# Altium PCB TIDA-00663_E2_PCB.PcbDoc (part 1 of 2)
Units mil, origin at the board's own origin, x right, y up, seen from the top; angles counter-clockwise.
Board outline 1968.5 x 1968.5 mil, 4 copper layers (Top Layer, Mid-Layer 1, Mid-Layer 2, Bottom Layer), stack 90 mil thick; 73 components, 52 nets, 290 pads, 111 vias.
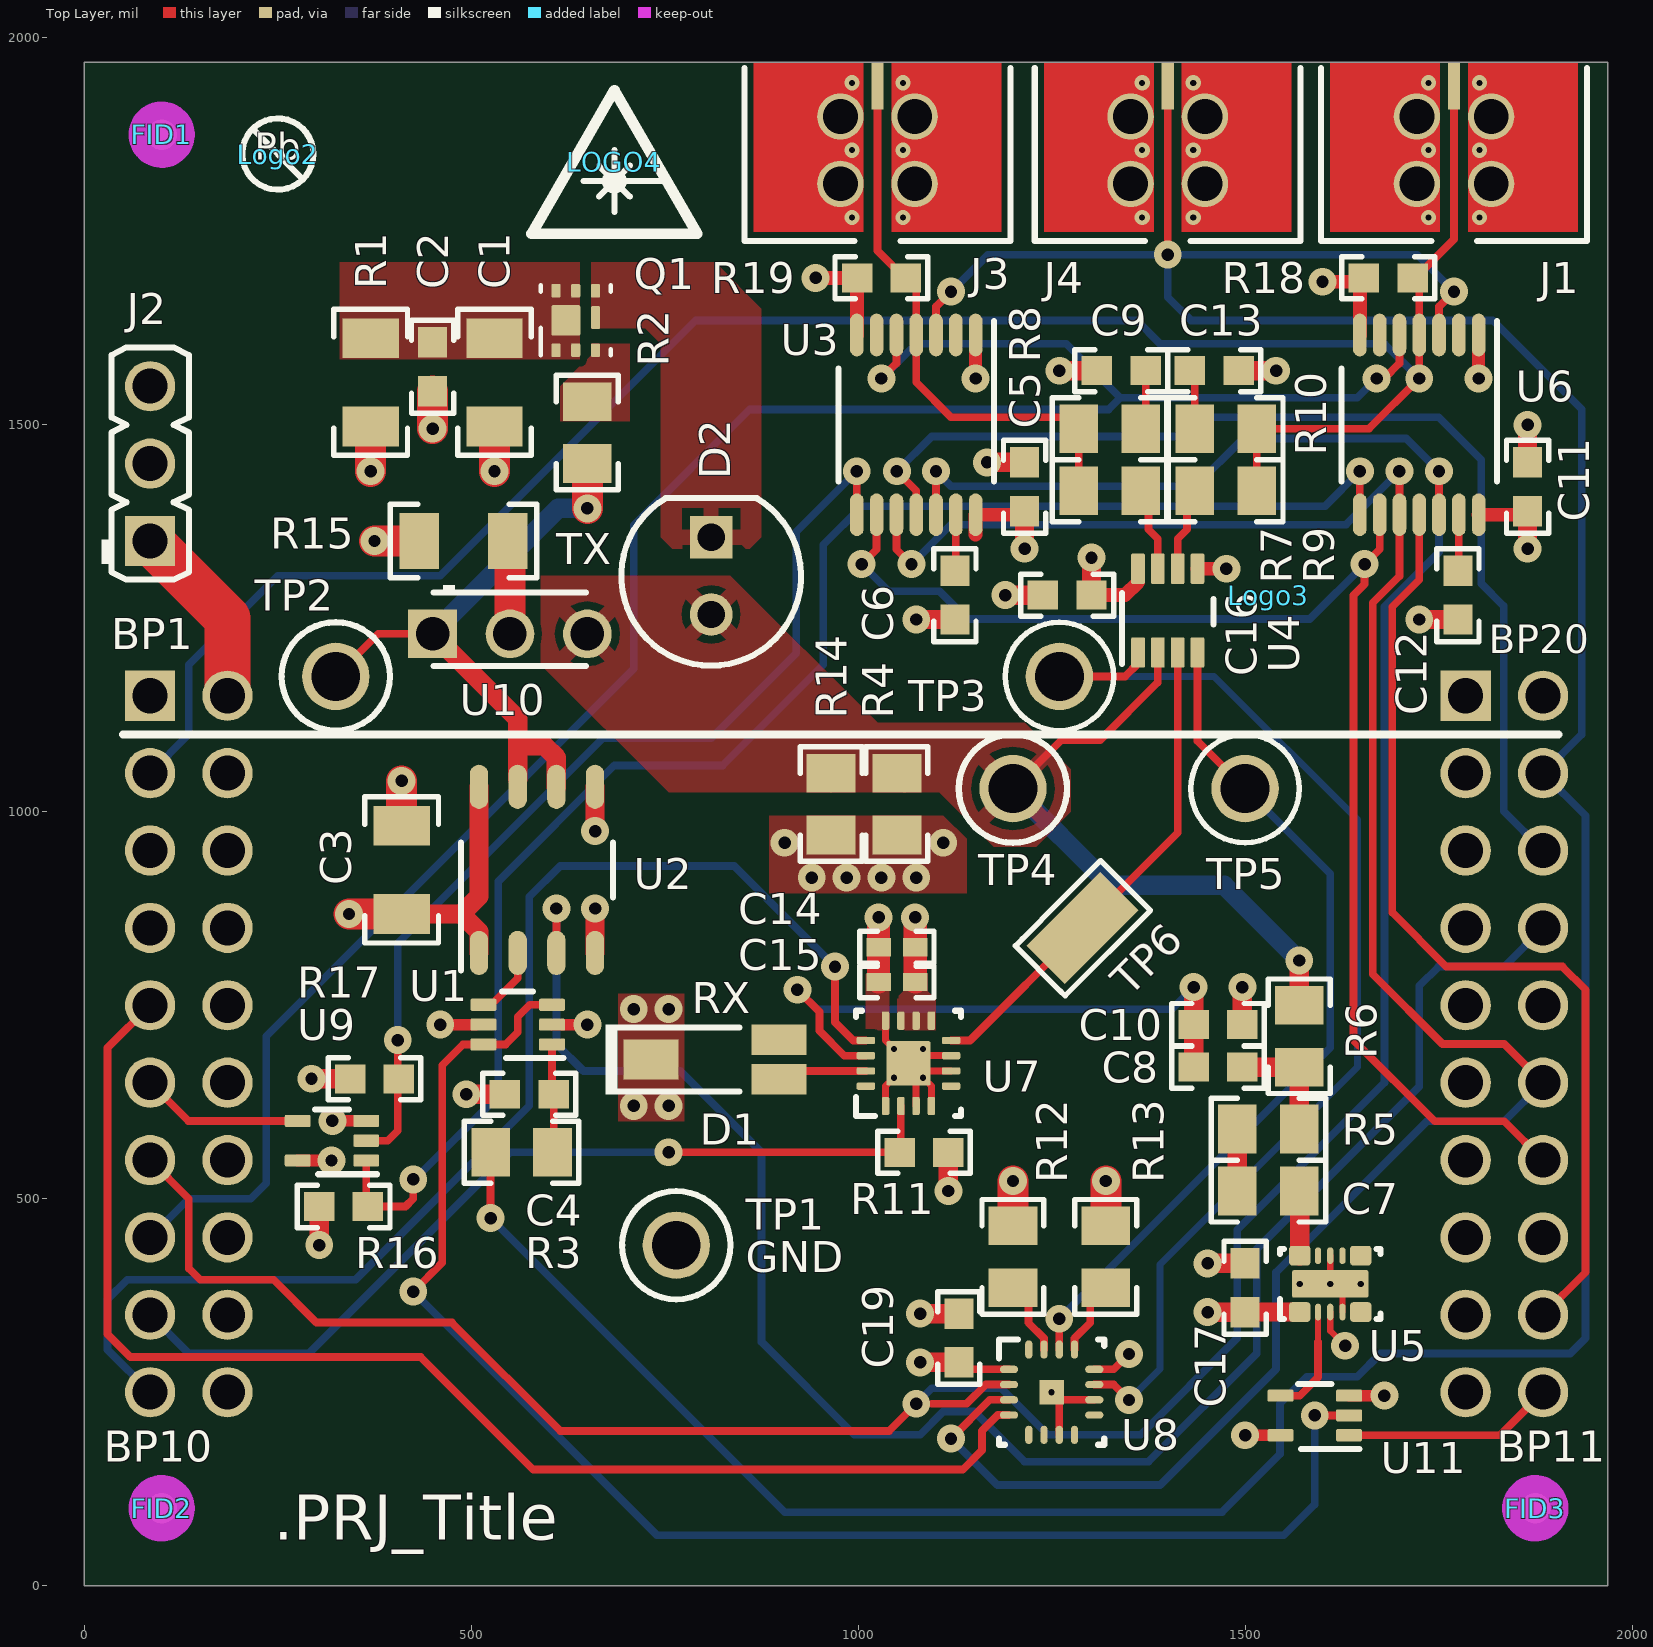
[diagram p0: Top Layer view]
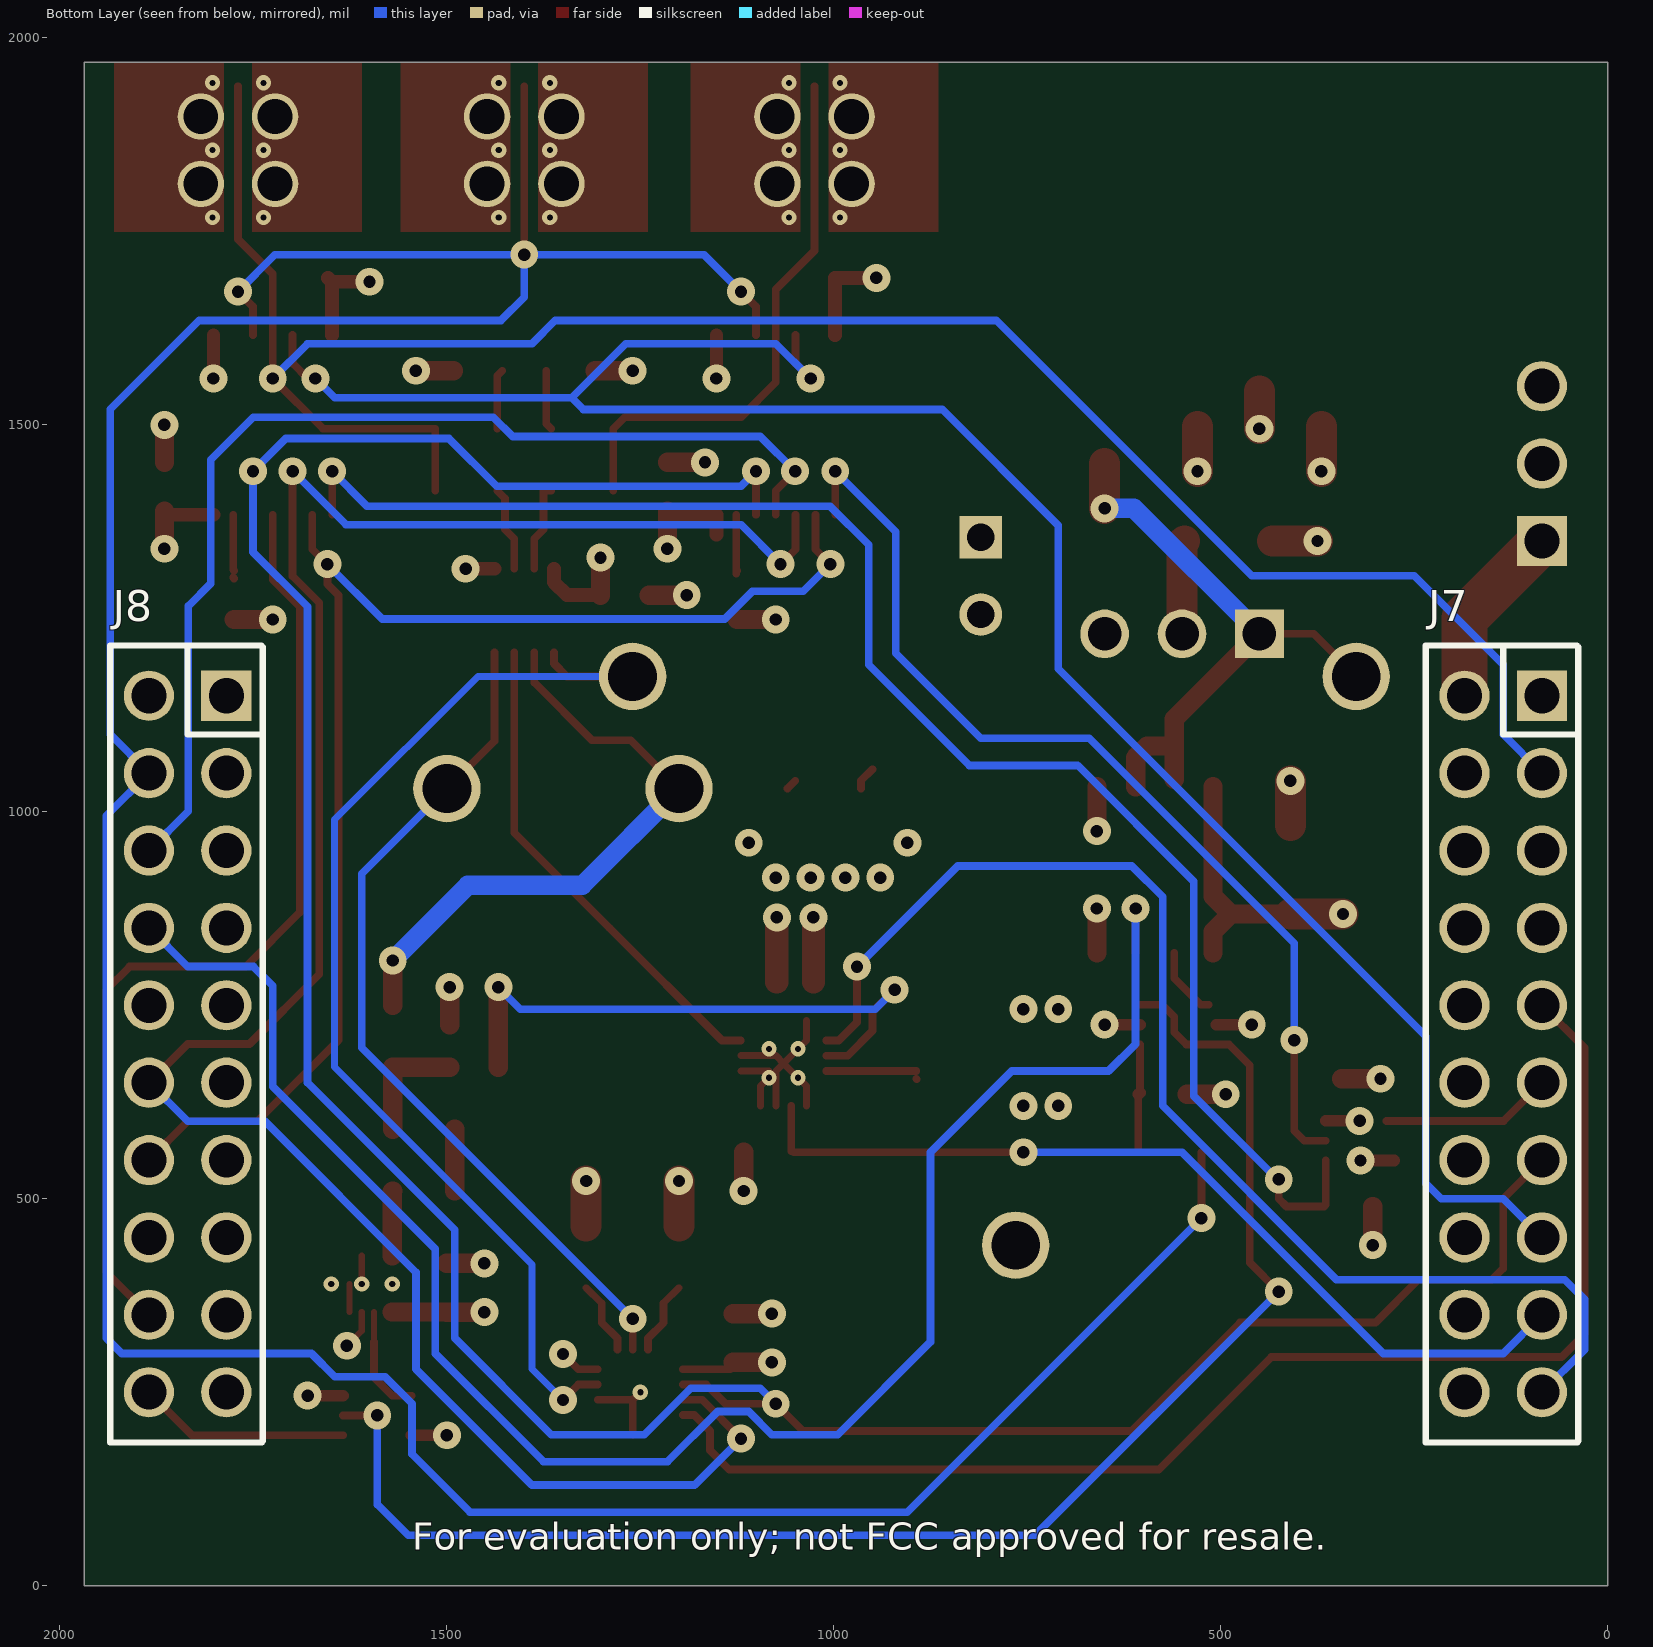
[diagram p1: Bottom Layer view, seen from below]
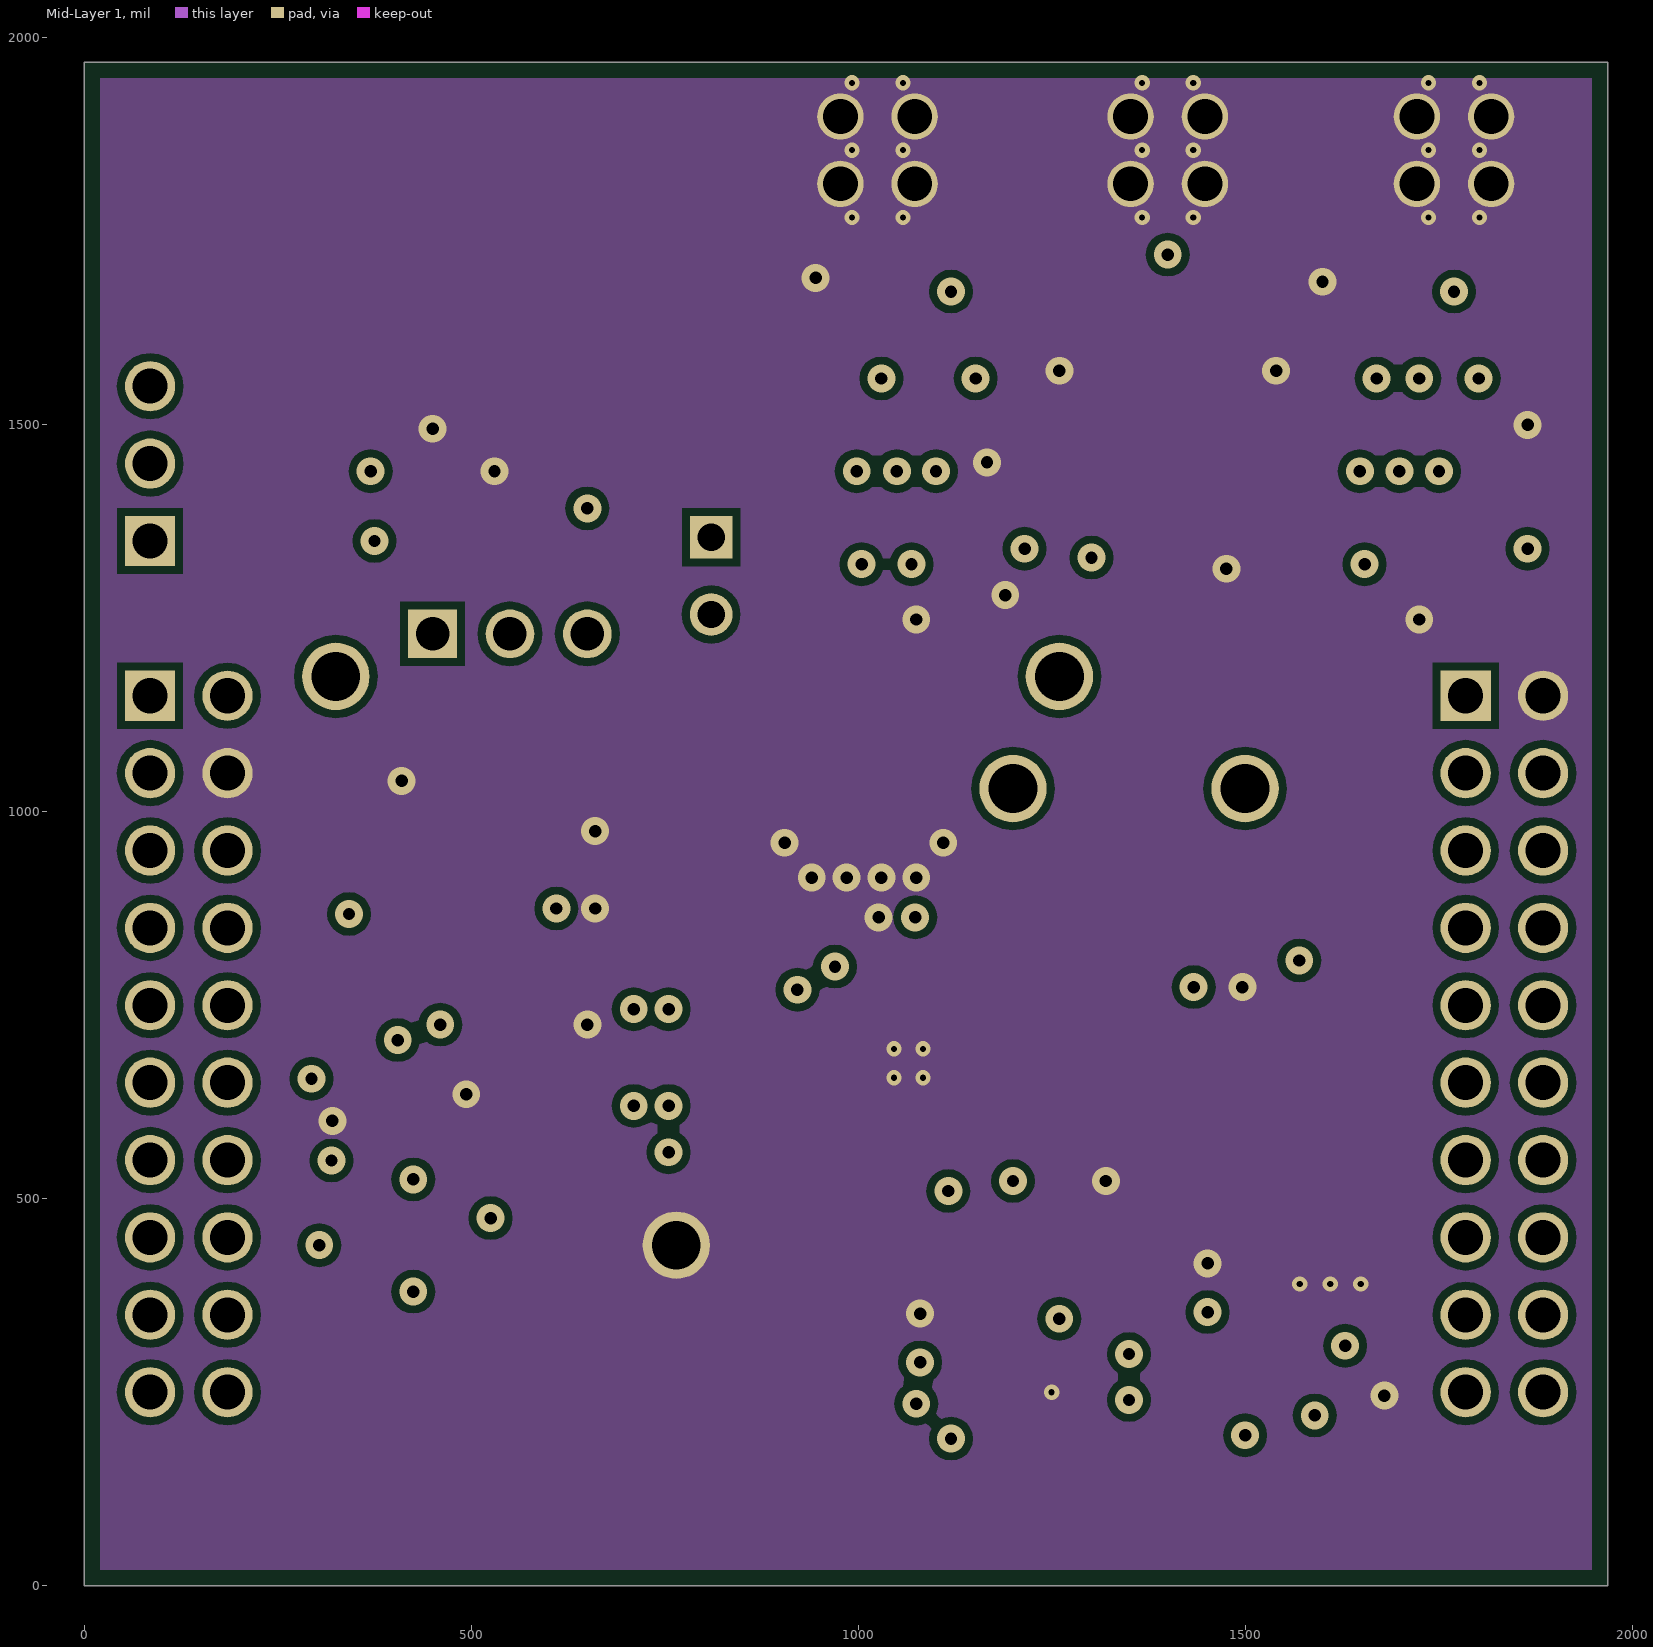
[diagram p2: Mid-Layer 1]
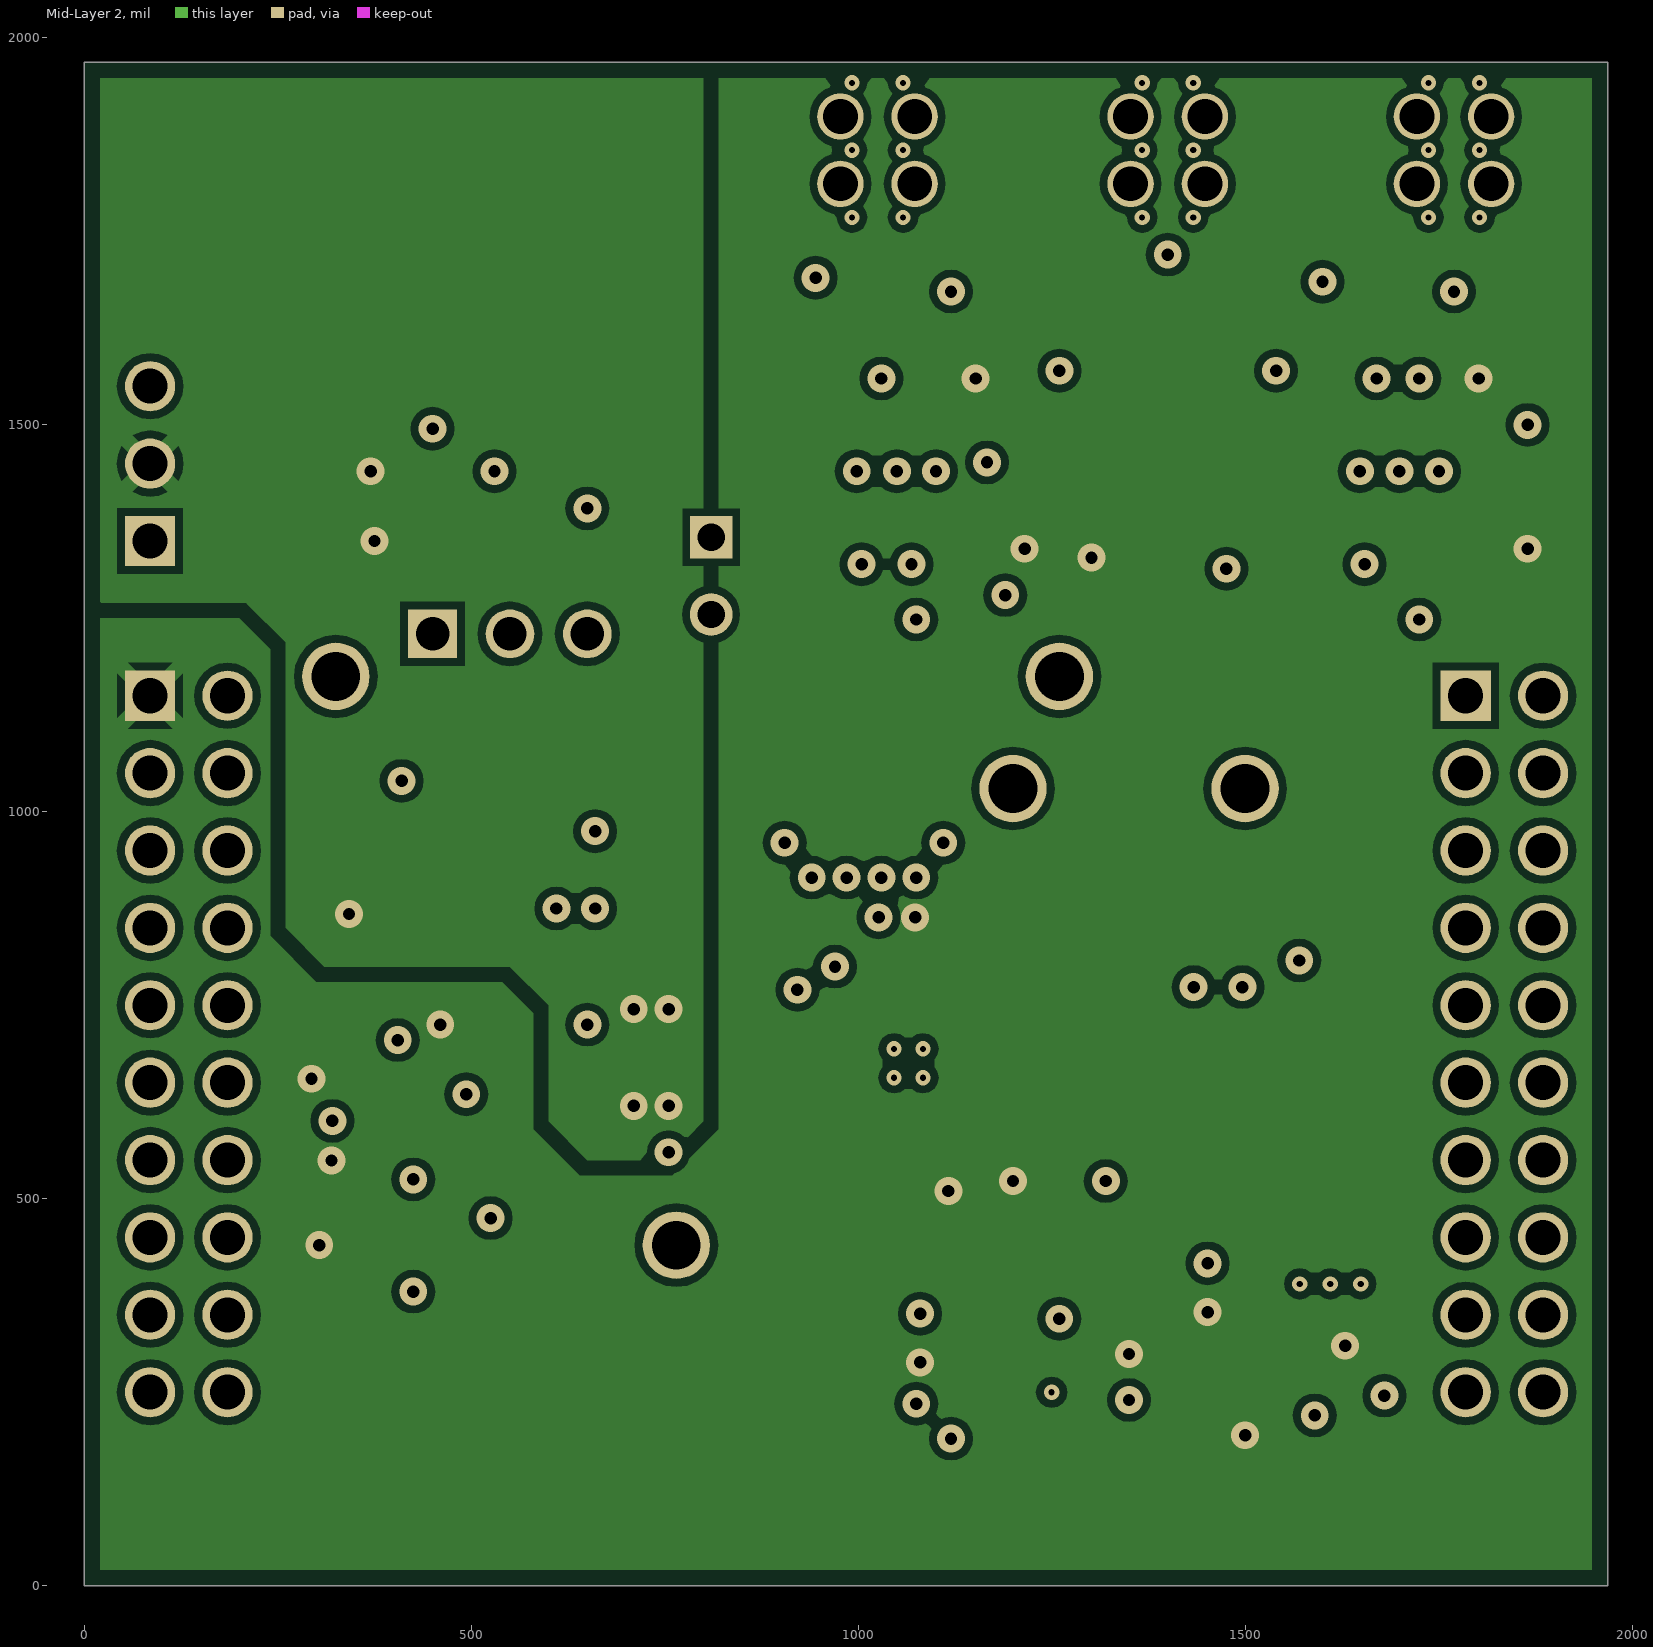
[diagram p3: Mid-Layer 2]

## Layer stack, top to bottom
Top Solder: solder mask 0.4, Solder Resist, Dk 3.5
Top Layer: signal copper 1.4
Dielectric1: core 59.2, FR-4, Dk 4.8
Mid-Layer 1: signal copper 1.4
Dielectric3: dielectric 12.6, FR-4, Dk 4.8
Mid-Layer 2: signal copper 1.4
Dielectric2: dielectric 12.6, FR-4, Dk 4.8
Bottom Layer: signal copper 1.4
Bottom Solder: solder mask 0.4, Solder Resist, Dk 3.5

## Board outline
0,0 0,1968.5 1968.5,1968.5 1968.5,0

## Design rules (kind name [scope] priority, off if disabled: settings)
AcuteAngle [All] p1: minimum=4.50000000000000E+0001 checktracksonly=FALSE
AssemblyTestPointUsage [All] p1: valid=2
BoardOutlineClearance [All] p1: gap=10 except(0: Arc-SplitContinuation Track-SplitContinuation SMDPad-SplitContinuation THPad-SplitContinuation Via-SplitContinuation Fill-SplitContinuation Poly-SplitContinuation Region-SplitContinuation Text-SplitContinuation; 20: Poly-OutlineEdge)
Clearance Clearance_Keepouts [((IsTrack Or IsArc) And Not InPoly) And IsFree and IsKeepOut vs ((IsTrack Or IsArc) And Not InPoly) And IsFree and IsKeepOut] p1: gap=0
Clearance Clearance_Poly [InPolygon] p2: gap=25 except(10: Arc-Poly Track-Poly SMDPad-Poly THPad-Poly Via-Poly Fill-Poly Poly-Poly)
Clearance [All] p3: gap=7.87 except(5.9: Track-Track Track-SMDPad SMDPad-SMDPad)
ComponentClearance ComponentClearance_MountingHoles_FiducialMarks [InComponentClass('Mounting Holes') vs InComponentClass('FiducialMark')] p1: gap=50 collisioncheckmode=3 verticalgap=10 showdistances=FALSE
ComponentClearance ComponentClearance_Shunt [InComponentClass('Header') vs InComponentClass('Shunt')] p2: gap=0 collisioncheckmode=3 verticalgap=0 showdistances=FALSE
ComponentClearance ComponentClearance_Logo [InComponentClass('Logo')] p3: gap=20 collisioncheckmode=3 verticalgap=10 showdistances=FALSE
ComponentClearance ComponentClearance_ScrewToNut [(HasFootprint('NY PMS 440 0025 PH')) vs (HasFootprint('Keystone_1902C'))] p4: gap=5 collisioncheckmode=3 verticalgap=10 showdistances=FALSE
ComponentClearance ComponentClearance_MountingHoles [InComponentClass('Mounting Holes')] p5: gap=250 collisioncheckmode=3 verticalgap=100000 showdistances=FALSE
ComponentClearance ComponentClearance_SmallPassives [HasFootprint('0201*') or HasFootprint('0402*') or HasFootprint('0508') or HasFootprint('0603*') or HasFootprint('0612') or HasFootprint('0805*') or HasFootprint('0815*') or HasFootprint('0830*') or HasFootprint('1206*') or HasFootprint('1210*') or HasFootprint('1808*') or HasFootprint('1812*') or HasFootprint('1825*') or HasFootprint('2010*') or HasFootprint('2220*') or HasFootprint('2225*') or HasFootprint('2512*') or HasFootprint('2728*') or HasFootprint('3518*') vs HasFootprint('0201*') or HasFootprint('0402*') or HasFootprint('0508') or HasFootprint('0603*') or HasFootprint('0612') or HasFootprint('0805*') or HasFootprint('0815*') or HasFootprint('0830*') or HasFootprint('1206*') or HasFootprint('1210*') or HasFootprint('1808*') or HasFootprint('1812*') or HasFootprint('1825*') or HasFootprint('2010*') or HasFootprint('2220*') or HasFootprint('2225*') or HasFootprint('2512*') or HasFootprint('2728*') or HasFootprint('3518*')] p6: gap=10 collisioncheckmode=3 verticalgap=10 showdistances=FALSE
ComponentClearance ComponentClearance_THtoSMT [IsThruComponent vs IsSMTComponent] p7: gap=20 collisioncheckmode=3 verticalgap=10 showdistances=FALSE
ComponentClearance ComponentClearance_THtoTH [IsThruComponent vs IsThruComponent] p8: gap=20 collisioncheckmode=3 verticalgap=30 showdistances=FALSE
ComponentClearance [All] p9: gap=10 collisioncheckmode=3 verticalgap=10 showdistances=FALSE
DiffPairsRouting [All] p1: maxlimit=100 minlimit=10 mostfreqgap=10 toplayer_minwidth=15 toplayer_maxwidth=15 toplayer_prefwidth=15 midlayer1_minwidth=15 midlayer1_maxwidth=15 midlayer1_prefwidth=15 midlayer2_minwidth=15 midlayer2_maxwidth=15 midlayer2_prefwidth=15 bottomlayer_minwidth=15 bottomlayer_maxwidth=15 bottomlayer_prefwidth=15 maxuncoupledlength=1000
FabricationTestPointUsage TestPointUsage [All] p1: valid=2 allowmultiple=FALSE
FabricationTestpoint Testpoint [All] p1: side=3 testpointundercomponent=TRUE minsize=40 maxsize=100 preferedsize=60 minholesize=0 maxholesize=40 preferedholesize=32 testpointgrid=1 allowsidetop=TRUE allowsidebottom=TRUE usegrid=TRUE gridtolerance=0.01
FanoutControl Fanout_LCC [IsLCC] p1: bgadir=Out bgaviamode=Centered fanoutstyle=Auto fanoutdirection=Alternating viagrid=1 // Fanout_LCC (Default Rule)
FanoutControl Fanout_BGA [IsBGA] p2: bgadir=Out bgaviamode=Centered fanoutstyle=Auto fanoutdirection=Alternating viagrid=1 // Fanout_BGA (Default Rule)
FanoutControl Fanout_Default [All] p4: bgadir=Out bgaviamode=Centered fanoutstyle=Auto fanoutdirection=Alternating viagrid=1 // Fanout_Default (Default Rule)
FanoutControl Fanout_Small [(CompPinCount < 5)] p5: bgadir=Out bgaviamode=Centered fanoutstyle=Auto fanoutdirection=OutThenIn viagrid=1 // Fanout_Small (Default Rule)
HoleSize [All] p1: absolutevalues=TRUE maxlimit=251 minlimit=7.87 maxpercent=80.000 minpercent=20.000
MinimumAnnularRing MinimumAnnularRing_ThermalPadVias [IsVia and InAnyComponent] p1: minimumring=5.91
MinimumAnnularRing [All] p2: minimumring=5
MinimumSolderMaskSliver MinimumSolderMaskSliver_Logo [InComponentClass('Logo') vs InComponentClass('Logo')] p1: minsoldermaskwidth=0.7
MinimumSolderMaskSliver [All] p2: minsoldermaskwidth=3.94
PlaneConnect [All] p1: planeconnectstyle=Relief reliefexpansion=10 reliefentries=4 reliefconductorwidth=10 reliefairgap=10
PolygonConnect PolygonConnect_D2 [HasPad('D2-1')] p1: connectstyle=Relief reliefconductorwidth=20 reliefentries=4 polygonreliefangle="90 Angle" airgapwidth=10
PolygonConnect PolygonConnect_Via_SMD [isVia or isSMTPin or (IsPad And InNet('GND'))] p2: connectstyle=Direct reliefconductorwidth=10 reliefentries=4 polygonreliefangle="90 Angle" airgapwidth=10
PolygonConnect [All] p3: connectstyle=Relief reliefconductorwidth=20 reliefentries=4 polygonreliefangle="45 Angle" airgapwidth=10
RoutingLayers [All] p1: top layer_v5=TRUE mid layer 1_v5=FALSE mid layer 2_v5=TRUE bottom layer_v5=TRUE
RoutingVias ThermalPadVias [IsVia and InAnyComponent] p1: holewidth=7.87 width=19.68 viastyle="Through Hole" minholewidth=7.87 minwidth=19.68 maxholewidth=12.99 maxwidth=23.62
RoutingVias [All] p2: holewidth=16 width=36 viastyle="Through Hole" minholewidth=7.87 minwidth=18 maxholewidth=16 maxwidth=36
ShortCircuit [InPadClass('U5')] p1: allowed=TRUE
SilkToBoardRegionClearance [Not ((IsComment or IsDesignator) And (Hide <> 'False')) and not InRegion(1000,500,4000,800)] p1:
SilkToSilkClearance SilkToSilkClearance_Pb-FreeLogo [(HasFootprint('Pb-Free_Overlay_Medium') OR HasFootprint('Pb-Free_Overlay_Small')) vs (HasFootprint('Pb-Free_Overlay_Medium') OR HasFootprint('Pb-Free_Overlay_Small'))] p1: silktosilkclearance=0
SilkToSilkClearance [All] p2: silktosilkclearance=4
SilkToSolderMaskClearance SilkToComponentPadClearance [IsPad and InAnycomponent] p1: minsilkscreentomaskgap=5 clearancetoexposedcopper=TRUE
SilkToSolderMaskClearance "Silk to Solder Mask Opening" [All] p2: minsilkscreentomaskgap=4 clearancetoexposedcopper=FALSE
SolderMaskExpansion [All] p1: expansion=1.97
Width [All] p1: maxlimit=100 minlimit=6 preferedwidth=8 minimp=50.000000 maximp=50.000000 favimp=50.000000 checkconnectedcopper=TRUE
13 further rules are at their usual default settings.

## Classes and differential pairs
component class TIDA-00663_E2_DesignForTest: C1 C2 D2 J1 J2 J3 J4 J7 J8 LOGO6 Q1 R1 R2 R4 R16 R17 R18 R19 TP1 U9
component class Header: J2
component class FiducialMark: FID1 FID2 FID3
component class TIDA-00663_E2_time_measure_shi: C3 C4 C5 C6 C7 C8 C9 C10 C11 C12 C13 C14 C15 C16 C17 C19 C? D1 D? LOGO4 LOGO? R3 R5 R6 R7 R8 R9 R10 R11 R12 R13 R14 R15 R? TP2 TP3 TP4 TP5 TP6 U1 U2 U3 U4 U5 U6 U7 U8 U10 U11
component class AssemblyNote: ZZ1 ZZ2 ZZ3 ZZ4
component class TIDA-00663_E2_EVM_Hardware: !PCB? FID1 FID2 FID3 Logo2 Logo3 ZZ1 ZZ2 ZZ3 ZZ4
pad class U5: U5-6 U5-7 U5-8 U5-9

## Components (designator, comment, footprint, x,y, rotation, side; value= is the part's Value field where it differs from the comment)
C1 "12061A102FAT2A" 1206 530,1555 r270 top
C2 "C1608X7R2A103M" 0603 450,1575 r270 top
C3 "GRM319R61H475KA12" 1206 410,925 r90 top
C4 "GRM1885C1H102FA01J" 0603 575,635 r180 top
C5 "0603YC104JAT2A" 0603 1215,1420 r90 top
C6 "EMK107B7105KA-T" 0603 1125,1280 r270 top
C7 "0805YD105KAT2A" 0805_HV 1530,510 r0 top
C8 "C0603X102K5RACTU" 0603 1465,670 r180 top
C9 "C0603X102K5RACTU" 0603 1340,1570 r180 top
C10 "C0603X102K5RACTU" 0603 1465,725 r0 top
C11 "0603YC104JAT2A" 0603 1865,1420 r90 top
C12 "EMK107B7105KA-T" 0603 1775,1280 r270 top
C13 "C0603X102K5RACTU" 0603 1460,1570 r0 top
C14 "GRM155R61A104KA01D" 0402 1050,825 r180 top
C15 "GRM155R61A104KA01D" 0402 1050,780 r180 top
C16 "0603YC104JAT2A" 0603 1270,1280 r180 top
C17 "EMK107B7105KA-T" 0603 1500,385 r90 top
C19 "0603YC104JAT2A" 0603 1130,320 r90 top
D1 "SFH 2400FA-Z" SFH2400FA 815,680 r0 top
D2 "SPL PL90_3" SPL_PL90_3_IR 810,1305 r270 top
FID1 "Fiducial" Fiducial10-20 100,1875 r0 top
FID2 "Fiducial" Fiducial10-20 100,100 r0 top
FID3 "Fiducial" Fiducial10-20 1875,100 r0 top
J1 "142-0761-881" Johnson_142-0761-881 1770,1855 r0 top
J2 "61300311121" WURTH_61300311121 85,1450 r90 top
J3 "142-0761-881" Johnson_142-0761-881 1025,1855 r0 top
J4 "142-0761-881" Johnson_142-0761-881 1400,1855 r0 top
J7 "SSW-110-23-F-D" CONN_SSW-110-23-F-D 135,700 r90 bottom locked
J8 "SSW-110-23-F-D" CONN_SSW-110-23-F-D 1835,700 r90 bottom locked
Logo2 "Pb-Free Symbol" Pb-Free_Overlay_Small 250,1850 r0 top
Logo3 "FCC disclaimer" FCC_disclaimer 1530,1280 r0 top
LOGO4 "LASER RADIATION" LaserWarning_Small 685,1840 r0 top
Q1 "CSD15571Q2" TRANS_NexFET_Q2 635,1635 r90 top
R1 "TNPW1206100RBEEA" 1206 370,1555 r270 top
R2 "MCR10EZPJ000" 0805_HV 650,1490 r90 top
R3 "ERJ-6GEYJ301V" 0805_HV 565,560 r0 top
R4 "WSL0805R0100FEA18" 0805_HV 1050,1010 r90 top
R5 "MCR10EZHJ000" 0805_HV 1530,590 r0 top
R6 "CRCW08051R00FKEA" 0805_HV 1570,710 r90 top
R7 "CRCW08050000Z0EA" 0805_HV 1325,1415 r180 top
R8 "CRCW08050000Z0EA" 0805_HV 1325,1495 r180 top
R9 "CRCW08050000Z0EA" 0805_HV 1475,1415 r0 top
R10 "CRCW08050000Z0EA" 0805_HV 1475,1495 r0 top
R11 "CRCW06031K00FKEA" 0603 1085,560 r0 top
R12 "RT0805BRD07142KL" 0805_HV 1200,425 r90 top
R13 "RT0805BRD07178KL" 0805_HV 1320,425 r90 top
R14 "WSL0805R0100FEA18" 0805_HV 965,1010 r90 top
R15 "TNPW1206100RBEEA" 1206 490,1350 r180 top
R16 "CRCW060310K0FKEA" 0603 335,490 r180 top
R17 "CRCW060310K0FKEA" 0603 375,655 r180 top
R18 "CRCW060350R0FKEA" 0603 1685,1690 r0 top
R19 "CRCW060350R0FKEA" 0603 1030,1690 r0 top
TP1 "GND" Keystone5006 765,440 r0 top
TP2 "5005" Keystone5005 325,1175 r0 top
TP3 "5129" Keystone5129 1260,1175 r90 top
TP4 "5013" Keystone5013 1200,1030 r90 top
TP5 "5129" Keystone5129 1500,1030 r90 top
TP6 "5015" Testpoint_Keystone_Miniature 1290,850 r45 top
U1 "SN74LVC2G14DCKR" DCK0006A_N 560,725 r180 top
U2 "UCC27321DR" D0008A_N 585,925 r90 top
U3 "TDC7200PWR" PW0014A_N 1075,1500 r270 top
U4 "TLV3502AIDCNR" DCN0008A_N 1400,1260 r90 top
U5 "TPS22968NDPUR" DPU0014A 1610,390 r90 top
U6 "TDC7200PWR" PW0014A_N 1725,1500 r270 top
U7 "OPA857IRGTR" RGT0016A 1065,675 r90 top
U8 "TPL0202-10MRTER" RTE0016D 1250,250 r0 top
U9 "SN74LVC1G08QDCKRQ1" DCK0005A_N 320,575 r180 top
U10 "SPL LL90_3" SPLLL90_3 550,1230 r0 top
U11 "SN74LVC1G08QDCKRQ1" DCK0005A_N 1590,220 r180 top
ZZ1 "This Assembly Note is for PCB labels only" AssemblyNoteLabel 188,3006 r0 top
ZZ2 "These assemblies are ESD sensitive, ESD precautions shall be observed." AssemblyNote 188,2897.11 r0 top
ZZ3 "These assemblies must be clean and free from flux and all contaminants. Use of no clean flux is not acceptable." AssemblyNote 188,2808.56 r0 top
ZZ4 "These assemblies must comply with workmanship standards IPC-A-610 Class 2, unless otherwise specified." AssemblyNote 188,2720 r0 top

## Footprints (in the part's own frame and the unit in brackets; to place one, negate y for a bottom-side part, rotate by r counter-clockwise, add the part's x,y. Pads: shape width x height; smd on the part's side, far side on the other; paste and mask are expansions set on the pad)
0402 [mm] "0402 from SM-752 data"
  rect 0.8x0.6 smd: 1(-0.6,0) 2(0.6,0)
  silkscreen extent -1.22,-0.52 1.22,0.52, body extent -0.55,-0.3 0.55,0.3, height 0.6
0603 [mm] "0603 from SM-752 data"
  rect 1x0.95 smd: 1(-0.8,0) 2(0.8,0)
  silkscreen extent -1.52,-0.69 1.52,0.69, body extent -0.87,-0.47 0.87,0.47, height 1
0805_HV [mil] "0805 with 30mil clearance between pads"
  rect 50x63 smd: 1(-40,0) 2(40,0)
  silkscreen extent -74,-40 74,40, body extent -43,-29 43,29, height 57
1206 [mm] "1206 from SM-752 data"
  rect 1.3x1.85 smd: 1(-1.45,0) 2(1.45,0)
  silkscreen extent -2.4,-1.21 2.4,1.21, body extent -1.7,-0.9 1.7,0.9, height 1.35
AssemblyNote [mil] "Assembly Note"
AssemblyNoteLabel [mil] "Assembly Note for PCB Labels"
CONN_SSW-110-23-F-D [mm] "SAMTEC"
  rect 1.65x1.65 hole 1.15: 1(11.43,-1.27)
  round 1.65 hole 1.15: 2(11.43,1.27) 3(8.89,-1.27) 4(8.89,1.27) 5(6.35,-1.27) 6(6.35,1.27) 7(3.81,-1.27) 8(3.81,1.27) 9(1.27,-1.27) 10(1.27,1.27) 11(-1.27,-1.27) 12(-1.27,1.27) 13(-3.81,-1.27) 14(-3.81,1.27) 15(-6.35,-1.27) 16(-6.35,1.27) 17(-8.89,-1.27) 18(-8.89,1.27) 19(-11.43,-1.27) 20(-11.43,1.27)
  silkscreen extent -13.08,-2.46 13.08,2.54, body extent -13,-2.51 13,2.54, height 8.59
D0008A_N [mm] "SOIC, 8-Leads, Body 4.9x3.9mm, Pitch 1.27mm, IPC Medium Density"
  oval 1.45x0.6 smd: 1(-2.725,1.905) 2(-2.725,0.635) 3(-2.725,-0.635) 4(-2.725,-1.905) 5(2.725,-1.905) 6(2.725,-0.635) 7(2.725,0.635) 8(2.725,1.905)
  silkscreen extent -3.3,-2.5 0.9,2.5, body extent -3,-2.45 3,2.45, height 1.63
DCK0005A_N [mm] "SOT353, 5-Leads, Body 2x1.3mm, Pitch 0.65mm, Lead Span 2.1mm, IPC Medium Density"
  rrect25% 0.85x0.4 smd: 1(-1.125,0.65) 2(-1.125,0) 3(-1.125,-0.65) 4(1.125,-0.65) 5(1.125,0.65)
  silkscreen extent -1.48,-1.02 0.55,1.1, body extent -1.14,-1 1.14,1, height 0.95
DCK0006A_N [mm] "SOT23, 6-Leads, Body 2x1.3mm, Pitch 0.65mm, Lead Span 2.1mm, IPC Medium Density"
  rrect25% 0.85x0.4 smd: 1(-1.125,0.65) 2(-1.125,0) 3(-1.125,-0.65) 4(1.125,-0.65) 5(1.125,0) 6(1.125,0.65)
  silkscreen extent -1.5,-1.09 0.51,1.09, body extent -1.14,-1 1.14,1, height 0.95
DCN0008A_N [mm] "SOP, 8-Leads, Body 2.9x1.6mm, Pitch 0.65mm, IPC Medium Density"
  rrect22% 1x0.45 smd: 1(-1.375,0.975) 2(-1.375,0.325) 3(-1.375,-0.325) 4(-1.375,-0.975) 5(1.375,-0.975) 6(1.375,-0.325) 7(1.375,0.325) 8(1.375,0.975)
  silkscreen extent -1.75,-1.5 0.58,1.5, body extent -1.41,-1.45 1.41,1.45, height 1.45
DPU0014A [mm] "SON-14"
  rrect50% 0.55x0.2 on Top Paste: 0(-0.925,-1.2) 0(-0.925,1.2) 0(0.925,-1.2) 0(0.925,1.2) 1(-0.925,-0.8) 1(-0.925,0.8) 1(0.925,-0.8) 1(0.925,0.8)
  rrect50% 0.55x0.2 on Top Solder: 0(-0.925,-1.2) 0(-0.925,1.2) 0(0.925,-1.2) 0(0.925,1.2) 1(-0.925,-0.8) 1(-0.925,0.8) 1(0.925,-0.8) 1(0.925,0.8)
  rrect33% 0.65x0.7 smd paste-0.35 mask-0.35: 1(-0.925,1) 2(-0.925,1) 6(-0.925,-1) 7(-0.925,-1) 8(0.925,-1) 9(0.925,-1) 13(0.925,1) 14(0.925,1)
  rrect50% 0.2x0.6 on Top Paste: 2(-0.75,1) 2(-0.75,-1) 2(0.75,1) 2(0.75,-1)
  rrect50% 0.2x0.6 on Top Solder: 2(-0.75,1) 2(-0.75,-1) 2(0.75,1) 2(0.75,-1)
  rrect100% 0.55x0.2 smd: 3(-0.925,0.4) 4(-0.925,0) 5(-0.925,-0.4) 10(0.925,-0.4) 11(0.925,0) 12(0.925,0.4)
  rrect11% 0.9x2.5 smd paste-0.5: 15(0,0)
  silkscreen extent -1.15,-1.65 1.15,1.65, body extent -1.05,-1.55 1.05,1.55, height 0.8
FCC_disclaimer [mil]
Fiducial10-20 [mm]
  round 1 smd mask+0.5: 1(0,0)
  Top Layer keep-out circle w1.178: c0,0 r0.5
Johnson_142-0761-881 [mil] "Connector, TH, End launch SMA"
  rect 16x60 smd: 1(0,82.5)
  round 60 hole 45 mask+0: 2(-48,43.5) 3(-48,-43.5) 4(48,-43.5) 5(48,43.5)
  Top Layer region: 18,-105.5 160,-105.5 160,112.5 18,112.5
  Top Layer region: -18,112.5 -160,112.5 -160,-105.5 -18,-105.5
  silkscreen extent -172,-117 172,106, body extent -124,-67 123,497, height 128
Keystone5005 [mil] "Keystone Compact loops"
  round 87 hole 63: 1(0,0)
  silkscreen extent -70,-70 70,70, body extent -63,-63 62,63, height 225
Keystone5006 [mil] "Keystone Compact loops"
  round 87 hole 63: 1(0,0)
  silkscreen extent -70,-70 70,70, body extent -63,-63 62,63, height 225
Keystone5013 [mil] "Keystone Multipurpose loops"
  round 87 hole 63: 1(0,0)
  silkscreen extent -70,-70 70,70, body extent -63,-63 63,62, height 319
Keystone5129 [mil] "Keystone Multipurpose loops"
  round 87 hole 63: 1(0,0)
  silkscreen extent -70,-70 70,70, body extent -63,-63 63,62, height 319
LaserWarning_Small [mil]
  silkscreen extent -107,-93 107,92
Pb-Free_Overlay_Small [mil]
  silkscreen extent -46,-46 46,46
PW0014A_N [mm] "TSOP, 14-Leads, Body 5x4.4mm, Pitch 0.65mm, IPC Medium Density"
  oval 1.4x0.45 smd: 1(-2.95,1.95) 2(-2.95,1.3) 3(-2.95,0.65) 4(-2.95,0) 5(-2.95,-0.65) 6(-2.95,-1.3) 7(-2.95,-1.95) 8(2.95,-1.95) 9(2.95,-1.3) 10(2.95,-0.65) 11(2.95,0) 12(2.95,0.65) 13(2.95,1.3) 14(2.95,1.95)
  silkscreen extent -3.4,-2.55 1.85,2.55, body extent -3.21,-2.5 3.21,2.5, height 1
RGT0016A [mm] "QFN, 16-Leads, Body 3x3mm, Pitch 0.5mm, Thermal Pad 1.45x1.45mm, TI Recommended"
  rrect42% 0.6x0.24 smd: 1(-1.4,0.75) 2(-1.4,0.25) 3(-1.4,-0.25) 4(-1.4,-0.75) 9(1.4,-0.75) 10(1.4,-0.25) 11(1.4,0.25) 12(1.4,0.75)
  rrect42% 0.24x0.6 smd: 5(-0.75,-1.4) 6(-0.25,-1.4) 7(0.25,-1.4) 8(0.75,-1.4) 13(0.75,1.4) 14(0.25,1.4) 15(-0.25,1.4) 16(-0.75,1.4)
  rrect7% 1.45x1.45 smd paste-0.725: 17(0,0)
  silkscreen extent -1.72,-1.73 1.72,1.73, body extent -1.57,-1.57 1.58,1.58, height 1.01
RTE0016D [mm] "QFN, 16-Leads, Body 3x3mm, Pitch 0.5mm"
  oval 0.6x0.24 smd: 1(-1.4,0.75) 2(-1.4,0.25) 3(-1.4,-0.25) 4(-1.4,-0.75) 9(1.4,-0.75) 10(1.4,-0.25) 11(1.4,0.25) 12(1.4,0.75)
  oval 0.24x0.6 smd: 5(-0.75,-1.4) 6(-0.25,-1.4) 7(0.25,-1.4) 8(0.75,-1.4) 13(0.75,1.4) 14(0.25,1.4) 15(-0.25,1.4) 16(-0.75,1.4)
  rect 0.8x0.8 smd paste-0.85: 17(0,0)
  silkscreen extent -1.72,-1.73 1.72,1.73, body extent -1.57,-1.57 1.58,1.58, height 0.81
SFH2400FA [mm] "SMD, 3-Leads, Body 2.6x2mm"
  rect 1.8x1.3 smd: 1(-2.1,0)
  rect 1.8x1 smd: 2(2.1,0.65) 3(2.1,-0.65)
  silkscreen extent -3.6,-1.15 0.8,1.15, body extent -1.35,-1.05 1.35,1.05, height 1.15
SPL_PL90_3_IR [mm] "TH, 2-Leads, Dia 4.9mm, Pin Spacing 2.54mm"
  rect 1.4x1.4 hole 0.9: 1(-1.27,0)
  round 1.4 hole 0.9: 2(1.27,0)
  silkscreen extent -2.55,-2.95 2.95,2.95, body extent -2.54,-2.96 2.95,2.96, height 8
SPLLL90_3 [mm] "TH, 3-Leads, Body 4.9x2.4mm, Pitch 2.54mm"
  rect 1.6x1.6 hole 1.1: 1(-2.54,0)
  round 1.6 hole 1.1: 2(0,0) 3(2.54,0)
  silkscreen extent -2.5,-1.05 2.5,1.6, body extent -2.84,-1.05 2.84,1.35, height 12.2
Testpoint_Keystone_Miniature [mil] "Miniature SMT test point"
  rect 135x70 smd: 1(0,0)
  silkscreen extent -78,-46 78,45, body extent -52,-20 52,20, height 61
TRANS_NexFET_Q2 [mm] "TI recommended land pattern M0167-01"
  rrect33% 0.45x0.3 smd: 1(-0.975,0.65) 2(-0.975,0) 3(-0.975,-0.65) 4(0.975,-0.65) 5(0.975,0) 6(0.975,0.65)
  rrect33% 0.75x0.3 smd paste-0.025: 7(0.095,-0.65)
  rrect11% 1x0.95 smd paste-0.025: 8(0,0.325)
  silkscreen extent -1.15,-1.15 1.15,1.15, body extent -1,-1 1,1, height 0.85
WURTH_61300311121 [mm] "Header, 2.54mm, 3x1, TH"
  rect 1.65x1.65 hole 1.15: 1(-2.54,0)
  round 1.65 hole 1.15: 2(0,0) 3(2.54,0)
  silkscreen extent -3.81,-1.27 3.81,1.6, body extent -3.81,-1.27 3.81,1.27, height 8.54

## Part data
C1: "CAP, CERM, 1000 pF, 100 V, +/- 1%, C0G/NP0, 1206"
C2: "CAP, CERM, 0.01 µF, 100 V, +/- 20%, X7R, 0603"
C3: "CAP, CERM, 4.7 µF, 50 V, +/- 10%, X5R, 1206"
C4: "CAP, CERM, 1000 pF, 50 V, +/- 1%, C0G/NP0, 0603"
C5 C11 C16 C19: "CAP, CERM, 0.1 µF, 16 V, +/- 5%, X7R, 0603"
C6 C12 C17: "CAP, CERM, 1 µF, 16 V, +/- 10%, X7R, 0603"
C7: "CAP, CERM, 1 µF, 16 V, +/- 10%, X5R, 0805"
C8 C9 C10 C13: "CAP, CERM, 1000 pF, 50 V, +/- 10%, X7R, 0603"
C14 C15: "CAP, CERM, 0.1 µF, 10 V, +/- 10%, X5R, 0402"
D1: "Silicon PIN Photodiode, SMD"
D2: "LED, Infrared, TH"
FID1 FID2 FID3: "Fiducial mark.  There is nothing to buy or mount."
J1 J3 J4: "Connector, TH, End launch SMA 50 ohm"
J2: "Header, 2.54 mm, 3x1, Gold, TH"
J7 J8: "Connector, Receptacle, 100mil, 10x2, Gold plated, TH"
Logo2: library part Pb-Free
Logo3: library part FCC_disclaimer, "FCC_disclaimer"
LOGO4: library part Laser_Warning, "Laser Warning Symbol"
Q1: "MOSFET, N-CH, 20 V, 10 A, SON 2x2mm"
R1 R15: "RES, 100, 0.1%, 0.25 W, 1206"
R2 R5 R7 R8 R9 R10: "RES, 0, 5%, 0.125 W, 0805"
R3: "RES, 300, 5%, 0.125 W, 0805"
R4 R14: "RES, 0.01, 1%, 0.25 W, 0805"
R6: "RES, 1.00, 1%, 0.125 W, 0805"
R11: "RES, 1.00 k, 1%, 0.1 W, 0603"
R12: "RES, 142 k, 0.1%, 0.125 W, 0805"
R13: "RES, 178 k, 0.1%, 0.125 W, 0805"
R16 R17: "RES, 10.0 k, 1%, 0.1 W, 0603"
R18 R19: "RES, 50, 1%, 0.1 W, 0603"
TP1: library part 5006, "Test Point, Compact, Black, TH"
TP2: "Test Point, Compact, Red, TH"
TP3 TP5: "Test Point, Multipurpose, Purple, TH"
TP4: "Test Point, Multipurpose, Orange, TH"
TP6: "Test Point, Miniature, SMT"
U1: "Dual Schmitt-Trigger Inverter, DCK0006A"
U2: "SINGLE 9-A HIGH SPEED LOW- SIDE MOSFET DRIVER WITH ENABLE, D0008A"
U3 U6: "Time-to-Digital Converter for Water, Gas, Heat Flow Metering Applications, PW0016A"
U4: "4.5 ns Rail-to-Rail, High-Speed Comparator, DCN0008A"
U5: "Dual Channel, Ultra-Low Resistance Load Switch, DPU0014A"
U7: "Ultralow-Noise, Wideband, Selectable-Feedback Resistance Transimpedance Amplifier, RGT0016A"
U8: "256-TAPS DUAL CHANNEL DIGITAL POTENTIOMETER WITH SPI INTERFACE AND NONVOLATILE MEMORY, RTE0016D"
U9 U11: "Single 2-Input Positive-AND Gate, DCK0005A"
U10: "Hybrid Pulsed Laser Diode with Integrated Driver Stage 70 W Peak Power, TH"
ZZ1: library part AssemblyNoteLabel
ZZ2 ZZ3 ZZ4: library part AssemblyNote

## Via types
v1: diameter 36, hole 16, Top Layer to Bottom Layer, tented both sides, 84 vias
v2: diameter 19.68, hole 7.87, Top Layer to Bottom Layer, 25 vias
v3: diameter 19.68, hole 7.87, Top Layer to Bottom Layer, tented top, 1 vias
v4: diameter 36, hole 16, Top Layer to Bottom Layer, 1 vias

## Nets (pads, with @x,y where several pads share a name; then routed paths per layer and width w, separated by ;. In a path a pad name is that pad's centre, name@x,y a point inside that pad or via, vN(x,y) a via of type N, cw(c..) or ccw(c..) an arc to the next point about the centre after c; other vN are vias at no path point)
5K_GAIN_SETTING_BP9_P3.5: J7.17 R11.1 U7.2 | length 1153.4
  Top Layer w10: v1(755,560) R11.1@1051.5,560 ; R11.1@1055,561.5 1055.16,561.65 U7.2@1055.16,619.88
  Bottom Layer w10: J7.17@85,350 135,300 290,300 550,560 v1(755,560)
ALIGNEMENT_MODE_SUPPLY: D2.1 Q1.4 Q1.7
BP11_CAL: J8.20 U11.1 | length 273.7
  Top Layer w10: U11.1@1634.29,194.41 1829.41,194.41 J8.20@1885,250
BP13_P2.6_SPI_CS_DISPLAY: J8.16
BP14_P1.5_UCB0SOMI: J8.14 U3.9 U6.9 | length 1782.7
  Top Layer w10: v1(1004.41,1320) 1023.82,1339.41 U3.9@1023.82,1383.86 ; U6.9@1673.82,1383.86 1673.82,1339.41 v1(1654.41,1320) 1654.41,1294.41 1640,1280 1640,705 1745,600 1835,600 J8.14@1885,550
  Bottom Layer w10: v1(1004.41,1320) 1039.41,1285 1105,1285 1140.87,1249.13 1583.54,1249.13 v1(1654.41,1320)
BP15_P1.4_UCB0SIMO: J8.12 U3.10 U6.10 U8.3 | length 2868.6
  Top Layer w10: U3.10@1049.41,1383.86 1049.41,1339.41 v1(1068.82,1320) ; v1(1120,190) 1170.16,240.16 U8.3@1194.88,240.16 ; v1(1699.41,1440) U6.10@1699.41,1383.86 1699.41,1304.41 1665,1270 1665,790 1755,700 1835,700 J8.12@1885,650
  Bottom Layer w10: v1(1068.82,1320) 1119.69,1370.87 1630.28,1370.87 v1(1699.41,1440) ; v1(1120,190) 1180,130 1390,130 1540,280 1540,405 1735,600 1835,600 J8.12@1885,650
BP_3.3V: C5.1 C11.1 C14.1 C15.1 C16.1 C17.1 C19.1 J7.1 R11.2 R12.2 R16.2 R17.2 U1.5 U3.1 U3.14 U4.8 U5.1@1570.63,353.58 U5.2@1570.63,353.58 U5.4 U6.1 U6.14 U7.9 U7.10 U7.11 U8.1 U8.12 U9.5 U11.5 | length 1265.3
  Top Layer w8: U5.4@1610,353.58 1610,329.25 v1(1629.25,310)
  Top Layer w10: C19.1@1130,288.5 C19.1@1133.98,284.53 ; C19.1@1133.98,279.53 U8.1@1194.88,279.53 ; U8.12@1305.12,279.53 1330.16,279.53 v1(1350,299.37)
  Top Layer w15: U9.5@275.71,549.41 v1(319.41,549.41) ; v1(460,725) U1.5@505.71,725 ; v1(1500,194.41) U11.5@1545.71,194.41
  Top Layer w17: v1(1151.77,1560) U3.1@1151.77,1616.14 ; v1(1801.77,1560) U6.1@1801.77,1616.14
  Top Layer w18: U3.14@1151.77,1358.23 U3.14@1151.77,1383.86 1210.35,1383.86 C5.1@1215,1388.5 ; C16.1@1301.5,1280 1345,1280 1361.61,1296.61 U4.8@1361.61,1314.13 ; U6.14@1801.77,1383.86 1860.35,1383.86 C11.1@1865,1388.5
  Top Layer w25: v1(293.5,655) R17.2@343.5,655 ; v1(303.5,440) R16.2@303.5,490 ; v1(1080,288.5) C19.1@1130,288.5 ; v1(1116.5,510) R11.2@1116.5,560 ; v1(1215,1340) C5.1@1215,1388.5 ; C16.1@1301.5,1280 v1(1301.5,1328.5) ; v1(1451.5,353.5) C17.1@1500,353.5 1500.08,353.58 U5.2@1570.63,353.58 ; v1(1865,1340) C11.1@1865,1388.5
  Top Layer w30: C15.1@1073.62,780 C14.1@1073.62,825 v1(1073.62,863.62)
  Top Layer w40: R12.2@1200,465 v1(1200,522.91)
BP_5V: J2.1 J7.2 | length 241.4
  Top Layer w60: J2.1@85,1350 185,1250 J7.2@185,1150
BP_GPIO_EN: J8.8 U2.3 | length 2340.4
  Top Layer w10: U2.3@610,817.72 v1(610,875)
  Bottom Layer w10: v1(610,875) 610,700 645,665 770,665 875,560 875,315 995,195 1080,195 1110,225 1150,225 1215,160 1375,160 1515,300 1515,435 1725,645 1725,775 1750,800 1835,800 J8.8@1885,850
BP_TRIG: J4.1 J8.4 R3.1 U3.3 U6.3 | length 4717.6
  Top Layer w10: v1(525,475) R3.1@525,560 ; U3.3@1100.59,1616.14 1100.59,1652.87 v1(1120,1672.28) ; v1(1400,1720) J4.1@1400,1937.5 ; U6.3@1750.59,1616.14 1750.59,1652.87 v1(1770,1672.28)
  Bottom Layer w10: v1(525,475) 905,95 1470,95 1545,170 1545,235 1580,270 1645,270 1675,300 1920,300 1940,320 1940,995 J8.4@1885,1050 1935,1100 1935,1520 1820,1635 1430,1635 1400,1665 v1(1400,1720) ; v1(1120,1672.28) 1167.72,1720 v1(1400,1720) ; v1(1770,1672.28) 1722.28,1720 v1(1400,1720)
DELAYED_CAL: U1.3 U1.6 U11.2 | length 1965.2
  Top Layer w10: v1(425,380) 462.63,417.63 462.63,672.63 489.41,699.41 U1.6@515.71,699.41 544.41,699.41 560,715 560,735 575.59,750.59 U1.3@604.29,750.59 ; v1(1590,220) U11.2@1634.29,220
  Bottom Layer w10: v1(425,380) 740,65 1550,65 1590,105 v1(1590,220)
DELAYED_TRIGGER: U1.4 U2.2 | length 91.3
  Top Layer w10: U1.4@515.71,750.59 525.59,750.59 560,785 U2.2@560,817.72
EXT_15V: J2.3
GATE_DRV: R2.1 TP2.1 U2.6 U2.7 U10.1 | length 795
  Top Layer w10: TP2.1@325,1175 380,1230 U10.1@450,1230
  Top Layer w25: U10.1@450,1230 560,1120 560,1090 ; U2.7@560,1042.28 560,1085 595,1085 610,1070 U2.6@610,1032.28
  Top Layer w40: v1(650,1392.09) R2.1@650,1450
  Bottom Layer w25: U10.1@450,1230 612.09,1392.09 v1(650,1392.09)
GND: C1.2 C2.2 C3.2 C4.2 C5.2 C6.2 C9.2 C10.2 C11.2 C12.2 C13.2 C14.2 C15.2 C16.2 C17.2 C19.2 J1.2 J1.3 J1.4 J1.5 J3.2 J3.3 J3.4 J3.5 J4.2 J4.3 J4.4 J4.5 J7.4 J8.2 R4.1 R13.2 R14.1 R18.1 R19.1 TP1.1 U1.2 U2.4 U2.5 U3.7 U4.5 U5.5 U5.11 U5.15 U6.7 U7.1 U7.3 U7.4 U7.6 U7.7 U7.12 U7.17 U8.7 U8.10 U8.17 U9.3 U11.3 | length 1892.3
  Top Layer w7.8: U5.5@1625.75,353.58 U5.15@1625.75,390
  Top Layer w8: v2(1610,390) U5.11@1610,426.42
  Top Layer w9: U7.1@1035.47,619.88 1035.47,645.47 U7.17@1065,675 ; U7.12@1035.47,730.12 1035.47,704.53 U7.17@1065,675 ; U7.3@1074.84,619.88 1074.84,665.16 U7.17@1065,675 ; v2(1083.7,656.3) 1094.53,645.47 U7.4@1094.53,619.88 ; U7.17@1083.7,665.16 U7.6@1120.12,665.16 ; U7.7@1120.12,684.84 1074.84,684.84 U7.17@1065,675
  Top Layer w10: v3(1250,250) U8.17@1259.84,240.16 ; U8.7@1259.84,194.88 U8.17@1259.84,240.16 ; U8.10@1305.12,240.16 U8.17@1259.84,240.16
  Top Layer w15: v1(320.59,600.59) U9.3@364.29,600.59 ; U1.2@604.29,725 v1(650,725) ; U11.3@1634.29,245.59 v1(1680,245.59)
  Top Layer w17: R19.1@998.23,1689.72 R19.1@998.5,1690
  Top Layer w18: v1(945,1690) R19.1@998.5,1690 ; U3.7@998.23,1616.14 R19.1@998.23,1689.72 ; U4.5@1438.39,1314.13 v4(1475.87,1314.13) ; v1(1600,1685) R18.1@1648.5,1685 ; U6.7@1648.23,1616.14 1648.23,1684.72 R18.1@1648.5,1685 ; R18.1@1653.5,1690 R18.1@1648.5,1685
  Top Layer w25: v1(493.5,635) C4.2@543.5,635 ; U2.4@660,817.72 v1(660,875) ; v1(660,975) U2.5@660,1032.28 ; v1(1075,1248.5) C6.2@1125,1248.5 ; v1(1080,351.5) C19.2@1130,351.5 ; v1(1166.5,1451.5) C5.2@1215,1451.5 ; v1(1190,1280) C16.2@1238.5,1280 ; v1(1260,1570) C9.2@1308.5,1570 ; v1(1451.5,416.5) C17.2@1500,416.5 ; C13.2@1491.5,1570 v1(1540,1570) ; C10.2@1496.5,725 v1(1496.5,773.5) ; v1(1725,1248.5) C12.2@1775,1248.5 ; C11.2@1865,1451.5 v1(1865,1500)
  Top Layer w30: C15.2@1026.38,780 C14.2@1026.38,825 v1(1026.38,863.62)
  Top Layer w40: C3.2@410,982.09 v1(410,1040) ; v1(450,1495) C2.2@450,1543.5 ; v1(530,1440) C1.2@530,1497.91 ; R13.2@1320,465 v1(1320,522.91)
  other v1: 940,915 985,915 1030,915 1075,915 905,960 1110,960
  other v2: 1570.63,390 1649.37,390 1046.3,656.3 1046.3,693.7 1083.7,693.7 992,1768 1058,1768 1367,1768 1433,1768 1737,1768 1803,1768 992,1855 1058,1855 1367,1855 1433,1855 1737,1855 1803,1855 992,1942 1058,1942 1367,1942 1433,1942 1737,1942 1803,1942
LASER_ON: D2.2 R4.2 R6.2 R14.2 TP4.1 U4.2 U10.3 | length 848
  Top Layer w10: R14.2@950,1055 965,1040 R14.2@965,1030 ; R4.2@1050,1040 R4.2@1060,1030 ; TP4.1@1200,1030 1262.5,1092.5 1312.5,1092.5 1387.2,1167.2 U4.2@1387.2,1205.87
  Top Layer w25: R6.2@1570,750 v1(1570,807.91)
  Bottom Layer w25: TP4.1@1200,1030 1325,905 1472.91,905 v1(1570,807.91)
